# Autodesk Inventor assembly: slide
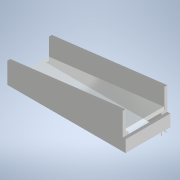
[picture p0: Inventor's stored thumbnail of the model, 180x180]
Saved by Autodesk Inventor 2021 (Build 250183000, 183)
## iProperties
Created: 2026-10
Part Number: slide
Document SubType Name: Assembly
Designer: alolo
Author: alolo
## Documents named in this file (5)
- C:\Users\alolo\Documents\Inventor\Design 1\slide.iam
- C:\Users\alolo\Documents\Inventor\Design 1\slide_rail.ipt
- C:\Users\alolo\Documents\Inventor\Design 1\slide_support.ipt
- C:\Users\alolo\Documents\Inventor\Design 1\slide_slant.ipt
- C:\Users\alolo\Documents\Inventor\Design 1\slide_back_support.ipt
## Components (6 placed, 4 different names)
1. slide_support:1 — Mate:1, Mate:2, Mate:3, Mate:4, Mate:5, Mate:6, Mate:7, Mate:8
2. slide_rail:1 — Mate:3, Mate:4, Mate:5, Mate:15
3. slide_slant:1 — Mate:6, Mate:7, Mate:8, Mate:9, Mate:10, Mate:11
4. slide_support:2 — Mate:9, Mate:10, Mate:11, Mate:12, Mate:13, Mate:14
5. slide_rail:2 — Mate:12, Mate:13, Mate:14, Mate:16, Mate:17
6. slide_back_support:1 — Mate:15, Mate:16, Mate:17
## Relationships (17: Mate 17)
- Mate:1: slide_support:1
- Mate:2: slide_support:1
- Mate:3: slide_support:1 ↔ slide_rail:1
- Mate:4: slide_support:1 ↔ slide_rail:1
- Mate:5: slide_support:1 ↔ slide_rail:1
- Mate:6: slide_support:1 ↔ slide_slant:1
- Mate:7: slide_support:1 ↔ slide_slant:1
- Mate:8: slide_support:1 ↔ slide_slant:1
- Mate:9: slide_slant:1 ↔ slide_support:2
- Mate:10: slide_slant:1 ↔ slide_support:2
- Mate:11: slide_slant:1 ↔ slide_support:2
- Mate:12: slide_support:2 ↔ slide_rail:2
- Mate:13: slide_support:2 ↔ slide_rail:2
- Mate:14: slide_support:2 ↔ slide_rail:2
- Mate:15: slide_rail:1 ↔ slide_back_support:1
- Mate:16: slide_rail:2 ↔ slide_back_support:1
- Mate:17: slide_rail:2 ↔ slide_back_support:1
